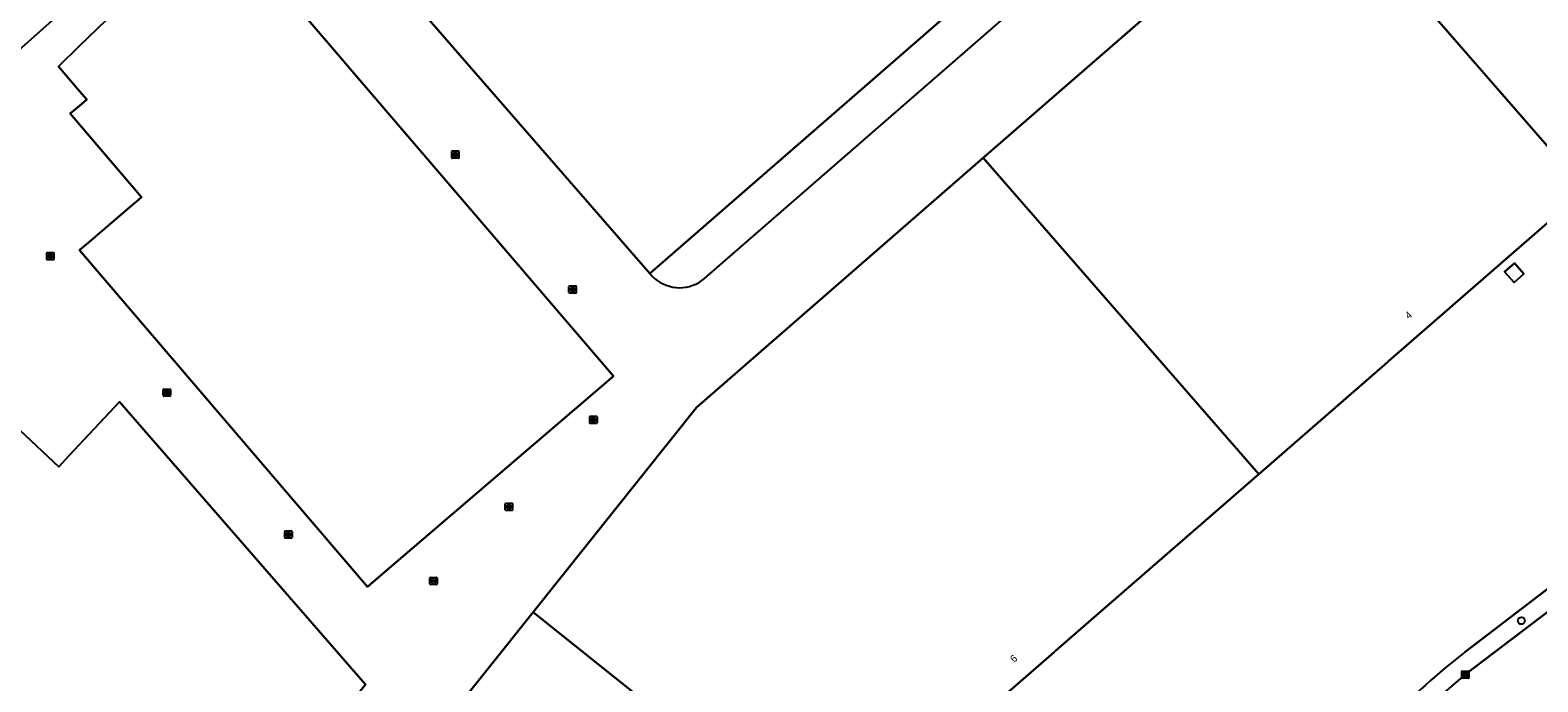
# Model space of a CAD drawing. Extents: x 156141 to 158132, y 385651 to 388333.
# Drawn here: x 156493.2 to 156702, y 386736.2 to 386826.5 of the extents above; entities that cross this region are included whole.
import ezdxf

# ---------------------------------------------------------------- set-up
doc = ezdxf.new("R2010")
doc.units = 0
for name, color, linetype in [('IMGEO_Berm_groen', 7, 'Continuous'), ('IMGEO_Boom', 7, 'Continuous'), ('IMGEO_Erf', 7, 'Continuous'), ('IMGEO_Groenvoorziening', 7, 'Continuous'), ('IMGEO_Hek', 7, 'Continuous'), ('IMGEO_Kolk', 7, 'Continuous'), ('IMGEO_Pand', 7, 'Continuous'), ('IMGEO_Pand_nummerreeks', 7, 'Continuous'), ('IMGEO_Pand_overbouw', 7, 'Continuous'), ('IMGEO_Rijbaan_lokaal_gesloten', 7, 'Continuous')]:
    doc.layers.add(name, color=color, linetype=linetype)

msp = doc.modelspace()

# ---------------------------------------------------------------- linework, layer by layer
at = {"layer": 'IMGEO_Berm_groen'}
for points in [[(156722.66, 386763.82), (156691.88, 386740.27)], [(156691.95, 386737.17), (156708.78, 386750), (156709.03, 386750.19), (156722.91, 386760.79)]]:
    msp.add_lwpolyline(points, dxfattribs=at)
for centre, radius, start, end in [((156758.44, 386655), 108.18, 127.9738, 143.0297), ((156759.5, 386654.29), 106.93, 129.1834, 140.1505)]:
    msp.add_arc(centre, radius, start, end, dxfattribs=at)
at = {"layer": 'IMGEO_Boom'}
msp.add_circle((156699.72, 386744.63), 0.489, dxfattribs=at)
at = {"layer": 'IMGEO_Erf'}
for points in [[(156579, 386792.74), (156536.65, 386841.45), (156528.4, 386850.93), (156539.01, 386860.16), (156540.51, 386861.46), (156539.64, 386862.47), (156541.88, 386864.4), (156542.76, 386863.4), (156544.26, 386864.71), (156553.86, 386857.56), (156554.4, 386856.9), (156564.64, 386845.13), (156582.75, 386860.85), (156583.79, 386861.76), (156573.53, 386873.55), (156565.27, 386883.02), (156568.32, 386885.63), (156567.99, 386886), (156571.25, 386888.77), (156592.61, 386907.35), (156643.5, 386848.89)], [(156562.82, 386745.82), (156585.47, 386774.18), (156625.19, 386808.77), (156670.44, 386848.17), (156724.8, 386895.5), (156762.97, 386851.71), (156754.18, 386844.05), (156753.97, 386843.86), (156725.69, 386819.23), (156725.5, 386819.06), (156708.6, 386804.34), (156681.33, 386780.59), (156681.14, 386780.43), (156663.35, 386764.94), (156635.2, 386740.45), (156635.02, 386740.29), (156627.59, 386733.83), (156608.17, 386709.52), (156594.29, 386692.16), (156594.13, 386691.97), (156570.73, 386662.69), (156570.57, 386662.48), (156563.29, 386653.38), (156517.91, 386689.59)], [(156573.96, 386778.5), (156540.63, 386750), (156539.88, 386749.35), (156539.32, 386750), (156500.02, 386795.98), (156500.69, 386796.56), (156500.87, 386796.72), (156507.65, 386802.53), (156507.84, 386802.69), (156508.6, 386803.34), (156500, 386813.38), (156498.7, 386814.9), (156500, 386815.99), (156501.01, 386816.84), (156500, 386818.01), (156497.07, 386821.42), (156500, 386824.27), (156502.48, 386826.69), (156506.95, 386831.05), (156513.62, 386837.54), (156518.51, 386831.86), (156524.17, 386836.69)], [(156698.75, 386794.18), (156700.06, 386792.68), (156698.71, 386791.5), (156697.4, 386793)]]:
    msp.add_lwpolyline(points, close=True, dxfattribs=at)
for points in [[(156500, 386831.2), (156491.57, 386823.65), (156483.14, 386815.4), (156480.48, 386812.82), (156481.2, 386811.98), (156475.71, 386805.5), (156458.53, 386785.23), (156416.67, 386732.53), (156478.51, 386695.24), (156485.28, 386691.16), (156502.21, 386680.95), (156502.3, 386681.12), (156504.13, 386680.02), (156508.42, 386677.43), (156596.8, 386624.11)], [(156440.94, 386745.41), (156441.14, 386745.62), (156436.99, 386749.49), (156473.36, 386788.27), (156497.13, 386765.98)], [(156497.13, 386765.98), (156498.54, 386767.48), (156505.52, 386774.95), (156539.63, 386735.79), (156502.86, 386689.7), (156473.05, 386707.68), (156477.03, 386711.95), (156467.31, 386721.05), (156467.13, 386720.89), (156467.24, 386720.39)], [(156691.88, 386740.27), (156722.66, 386763.82)]]:
    msp.add_lwpolyline(points, dxfattribs=at)
msp.add_arc((156758.44, 386655), 108.18, 127.9738, 143.0297, dxfattribs=at)
at = {"layer": 'IMGEO_Groenvoorziening'}
msp.add_lwpolyline([(156484.3, 386831.99), (156487.09, 386828.79), (156488.42, 386827.26), (156491.57, 386823.65), (156500, 386831.2), (156500.6, 386831.73), (156507.07, 386837.56), (156510.79, 386840.87), (156506.2, 386846.18)], dxfattribs=at)
at = {"layer": 'IMGEO_Hek'}
msp.add_lwpolyline([(156722.66, 386763.82), (156691.88, 386740.27)], dxfattribs=at)
msp.add_arc((156758.44, 386655), 108.18, 127.9738, 143.0297, dxfattribs=at)
at = {"layer": 'IMGEO_Kolk'}
for p, q in [((156551.56, 386808.8), (156551.56, 386809.65)), ((156551.64, 386809.72), (156552.49, 386809.72)), ((156552.49, 386808.72), (156551.64, 386808.72)), ((156551.82, 386809.22), (156551.82, 386809.23)), ((156551.86, 386809.27), (156552.26, 386809.27)), ((156552.26, 386809.18), (156551.86, 386809.18)), ((156552.05, 386809.5), (156552.08, 386809.5)), ((156552.07, 386808.94), (156552.05, 386808.94)), ((156552.31, 386809.23), (156552.31, 386809.22)), ((156552.56, 386809.65), (156552.56, 386808.8)), ((156495.46, 386794.72), (156495.46, 386795.57)), ((156495.53, 386795.64), (156496.38, 386795.64)), ((156496.38, 386794.64), (156495.53, 386794.64)), ((156495.71, 386795.14), (156495.71, 386795.15)), ((156496.15, 386795.1), (156495.75, 386795.1)), ((156495.76, 386795.19), (156496.16, 386795.19)), ((156495.94, 386795.42), (156495.97, 386795.42)), ((156495.97, 386794.86), (156495.94, 386794.86)), ((156496.2, 386795.15), (156496.2, 386795.14)), ((156496.46, 386795.57), (156496.46, 386794.72)), ((156567.8, 386790.11), (156567.8, 386790.96)), ((156567.87, 386791.04), (156568.72, 386791.04)), ((156568.72, 386790.04), (156567.87, 386790.04)), ((156568.05, 386790.53), (156568.05, 386790.54)), ((156568.49, 386790.49), (156568.09, 386790.49)), ((156568.1, 386790.58), (156568.5, 386790.58)), ((156568.28, 386790.82), (156568.31, 386790.82)), ((156568.31, 386790.26), (156568.28, 386790.26)), ((156568.54, 386790.54), (156568.54, 386790.53)), ((156568.8, 386790.96), (156568.8, 386790.11)), ((156511.6, 386775.82), (156511.6, 386776.67)), ((156511.67, 386776.74), (156512.52, 386776.74)), ((156512.52, 386775.74), (156511.67, 386775.74)), ((156511.86, 386776.24), (156511.86, 386776.25)), ((156511.9, 386776.29), (156512.3, 386776.29)), ((156512.29, 386776.2), (156511.9, 386776.2)), ((156512.11, 386775.96), (156512.08, 386775.96)), ((156512.09, 386776.52), (156512.11, 386776.52)), ((156512.34, 386776.25), (156512.34, 386776.24)), ((156512.6, 386776.67), (156512.6, 386775.82)), ((156570.68, 386772.05), (156570.68, 386772.9)), ((156570.75, 386772.98), (156571.6, 386772.98)), ((156571.6, 386771.98), (156570.75, 386771.98)), ((156570.93, 386772.47), (156570.93, 386772.48)), ((156571.37, 386772.43), (156570.97, 386772.43)), ((156570.98, 386772.52), (156571.37, 386772.52)), ((156571.16, 386772.76), (156571.19, 386772.76)), ((156571.19, 386772.2), (156571.16, 386772.2)), ((156571.42, 386772.48), (156571.42, 386772.47)), ((156571.68, 386772.9), (156571.68, 386772.05)), ((156558.98, 386759.99), (156558.98, 386760.84)), ((156559.06, 386760.92), (156559.91, 386760.92)), ((156559.47, 386760.7), (156559.5, 386760.7)), ((156559.98, 386760.84), (156559.98, 386759.99)), ((156559.91, 386759.92), (156559.06, 386759.92)), ((156559.24, 386760.41), (156559.24, 386760.42)), ((156559.28, 386760.46), (156559.68, 386760.46)), ((156559.68, 386760.37), (156559.28, 386760.37)), ((156559.49, 386760.14), (156559.47, 386760.14)), ((156559.73, 386760.42), (156559.73, 386760.41)), ((156528.44, 386756.16), (156528.44, 386757.01)), ((156528.51, 386757.08), (156529.36, 386757.08)), ((156528.69, 386756.58), (156528.69, 386756.59)), ((156529.13, 386756.54), (156528.73, 386756.54)), ((156528.74, 386756.63), (156529.13, 386756.63)), ((156528.92, 386756.86), (156528.95, 386756.86)), ((156528.95, 386756.3), (156528.92, 386756.3)), ((156529.18, 386756.59), (156529.18, 386756.58)), ((156529.44, 386757.01), (156529.44, 386756.16)), ((156529.36, 386756.08), (156528.51, 386756.08)), ((156548.54, 386749.71), (156548.54, 386750.57)), ((156548.61, 386750.64), (156549.47, 386750.64)), ((156548.8, 386750.13), (156548.8, 386750.15)), ((156548.84, 386750.18), (156549.24, 386750.18)), ((156549.23, 386750.1), (156548.84, 386750.1)), ((156549.03, 386750.42), (156549.05, 386750.42)), ((156549.28, 386750.15), (156549.28, 386750.13)), ((156549.54, 386750.57), (156549.54, 386749.71)), ((156549.47, 386749.64), (156548.61, 386749.64)), ((156549.05, 386749.86), (156549.02, 386749.86)), ((156691.46, 386736.75), (156691.46, 386737.6)), ((156691.53, 386737.67), (156692.38, 386737.67)), ((156692.46, 386737.6), (156692.46, 386736.75)), ((156692.38, 386736.67), (156691.53, 386736.67)), ((156691.71, 386737.17), (156691.71, 386737.18)), ((156692.15, 386737.13), (156691.75, 386737.13)), ((156691.76, 386737.22), (156692.15, 386737.22)), ((156691.94, 386737.45), (156691.97, 386737.45)), ((156691.97, 386736.89), (156691.94, 386736.89)), ((156692.2, 386737.18), (156692.2, 386737.17))]:
    msp.add_line(p, q, dxfattribs=at)
for points in [[(156551.56, 386808.8), (156551.56, 386809.65)], [(156551.64, 386809.72), (156552.49, 386809.72)], [(156552.49, 386808.72), (156551.64, 386808.72)], [(156552.56, 386809.65), (156552.56, 386808.8)], [(156495.46, 386794.72), (156495.46, 386795.57)], [(156495.53, 386795.64), (156496.38, 386795.64)], [(156496.38, 386794.64), (156495.53, 386794.64)], [(156496.46, 386795.57), (156496.46, 386794.72)], [(156567.8, 386790.11), (156567.8, 386790.96)], [(156567.87, 386791.04), (156568.72, 386791.04)], [(156568.72, 386790.04), (156567.87, 386790.04)], [(156568.8, 386790.96), (156568.8, 386790.11)], [(156511.6, 386775.82), (156511.6, 386776.67)], [(156511.67, 386776.74), (156512.52, 386776.74)], [(156512.52, 386775.74), (156511.67, 386775.74)], [(156512.6, 386776.67), (156512.6, 386775.82)], [(156570.68, 386772.05), (156570.68, 386772.9)], [(156570.75, 386772.98), (156571.6, 386772.98)], [(156571.6, 386771.98), (156570.75, 386771.98)], [(156571.68, 386772.9), (156571.68, 386772.05)], [(156558.98, 386759.99), (156558.98, 386760.84)], [(156559.06, 386760.92), (156559.91, 386760.92)], [(156559.98, 386760.84), (156559.98, 386759.99)], [(156559.91, 386759.92), (156559.06, 386759.92)], [(156528.44, 386756.16), (156528.44, 386757.01)], [(156528.51, 386757.08), (156529.36, 386757.08)], [(156529.44, 386757.01), (156529.44, 386756.16)], [(156529.36, 386756.08), (156528.51, 386756.08)], [(156548.54, 386749.71), (156548.54, 386750.57)], [(156548.61, 386750.64), (156549.47, 386750.64)], [(156549.54, 386750.57), (156549.54, 386749.71)], [(156549.47, 386749.64), (156548.61, 386749.64)], [(156691.46, 386736.75), (156691.46, 386737.6)], [(156691.53, 386737.67), (156692.38, 386737.67)], [(156692.46, 386737.6), (156692.46, 386736.75)], [(156692.38, 386736.67), (156691.53, 386736.67)]]:
    msp.add_lwpolyline(points, dxfattribs=at)
for centre, radius, start, end in [((156551.64, 386809.65), 0.0765, 91.552, 178.448), ((156551.64, 386809.65), 0.0765, 91.552, 178.448), ((156551.64, 386808.8), 0.0765, 181.552, 268.448), ((156551.64, 386808.8), 0.0765, 181.552, 268.448), ((156551.86, 386809.23), 0.0403, 85.8775, 175.7526), ((156551.86, 386809.22), 0.0366, 178.938, 274.7102), ((156552.27, 386809.23), 0.0386, 1.7309, 96.639), ((156552.26, 386809.22), 0.043, 264.8664, 352.4533), ((156552.49, 386809.65), 0.0765, 1.552, 88.448), ((156552.49, 386809.65), 0.0765, 1.552, 88.448), ((156552.49, 386808.8), 0.0765, 271.552, 358.448), ((156552.49, 386808.8), 0.0765, 271.552, 358.448), ((156495.53, 386795.57), 0.0765, 91.552, 178.448), ((156495.53, 386795.57), 0.0765, 91.552, 178.448), ((156495.53, 386794.72), 0.0765, 181.552, 268.448), ((156495.53, 386794.72), 0.0765, 181.552, 268.448), ((156495.76, 386795.15), 0.0403, 85.8775, 175.7526), ((156495.75, 386795.14), 0.0366, 178.938, 274.7102), ((156496.16, 386795.14), 0.043, 264.8664, 352.4533), ((156496.16, 386795.15), 0.0386, 1.7309, 96.639), ((156496.38, 386795.57), 0.0765, 1.552, 88.448), ((156496.38, 386795.57), 0.0765, 1.552, 88.448), ((156496.38, 386794.72), 0.0765, 271.552, 358.448), ((156496.38, 386794.72), 0.0765, 271.552, 358.448), ((156567.87, 386790.96), 0.0765, 91.552, 178.448), ((156567.87, 386790.96), 0.0765, 91.552, 178.448), ((156567.87, 386790.11), 0.0765, 181.552, 268.448), ((156567.87, 386790.11), 0.0765, 181.552, 268.448), ((156568.1, 386790.54), 0.0403, 85.8775, 175.7526), ((156568.09, 386790.53), 0.0366, 178.938, 274.7102), ((156568.5, 386790.54), 0.043, 264.8664, 352.4533), ((156568.5, 386790.54), 0.0386, 1.7309, 96.639), ((156568.72, 386790.96), 0.0765, 1.552, 88.448), ((156568.72, 386790.96), 0.0765, 1.552, 88.448), ((156568.72, 386790.11), 0.0765, 271.552, 358.448), ((156568.72, 386790.11), 0.0765, 271.552, 358.448), ((156511.67, 386776.67), 0.0765, 91.552, 178.448), ((156511.67, 386776.67), 0.0765, 91.552, 178.448), ((156511.67, 386775.82), 0.0765, 181.552, 268.448), ((156511.67, 386775.82), 0.0765, 181.552, 268.448), ((156511.9, 386776.25), 0.0403, 85.8775, 175.7526), ((156511.89, 386776.24), 0.0366, 178.938, 274.7102), ((156512.3, 386776.24), 0.043, 264.8664, 352.4533), ((156512.3, 386776.25), 0.0386, 1.7309, 96.639), ((156512.52, 386776.67), 0.0765, 1.552, 88.448), ((156512.52, 386776.67), 0.0765, 1.552, 88.448), ((156512.52, 386775.82), 0.0765, 271.552, 358.448), ((156512.52, 386775.82), 0.0765, 271.552, 358.448), ((156570.75, 386772.9), 0.0765, 91.552, 178.448), ((156570.75, 386772.9), 0.0765, 91.552, 178.448), ((156570.75, 386772.05), 0.0765, 181.552, 268.448), ((156570.75, 386772.05), 0.0765, 181.552, 268.448), ((156570.97, 386772.48), 0.0403, 85.8775, 175.7526), ((156570.97, 386772.47), 0.0366, 178.938, 274.7102), ((156571.38, 386772.48), 0.0386, 1.7309, 96.639), ((156571.38, 386772.48), 0.043, 264.8664, 352.4533), ((156571.6, 386772.9), 0.0765, 1.552, 88.448), ((156571.6, 386772.9), 0.0765, 1.552, 88.448), ((156571.6, 386772.05), 0.0765, 271.552, 358.448), ((156571.6, 386772.05), 0.0765, 271.552, 358.448), ((156559.06, 386760.84), 0.0765, 91.552, 178.448), ((156559.06, 386760.84), 0.0765, 91.552, 178.448), ((156559.91, 386760.84), 0.0765, 1.552, 88.448), ((156559.91, 386760.84), 0.0765, 1.552, 88.448), ((156559.06, 386759.99), 0.0765, 181.552, 268.448), ((156559.06, 386759.99), 0.0765, 181.552, 268.448), ((156559.28, 386760.42), 0.0403, 85.8775, 175.7526), ((156559.28, 386760.41), 0.0366, 178.938, 274.7102), ((156559.69, 386760.42), 0.0386, 1.7309, 96.639), ((156559.68, 386760.42), 0.043, 264.8664, 352.4533), ((156559.91, 386759.99), 0.0765, 271.552, 358.448), ((156559.91, 386759.99), 0.0765, 271.552, 358.448), ((156528.51, 386757.01), 0.0765, 91.552, 178.448), ((156528.51, 386757.01), 0.0765, 91.552, 178.448), ((156528.73, 386756.59), 0.0403, 85.8775, 175.7526), ((156528.73, 386756.58), 0.0366, 178.938, 274.7102), ((156529.14, 386756.59), 0.0386, 1.7309, 96.639), ((156529.14, 386756.58), 0.043, 264.8664, 352.4533), ((156529.36, 386757.01), 0.0765, 1.552, 88.448), ((156529.36, 386757.01), 0.0765, 1.552, 88.448), ((156528.51, 386756.16), 0.0765, 181.552, 268.448), ((156528.51, 386756.16), 0.0765, 181.552, 268.448), ((156529.36, 386756.16), 0.0765, 271.552, 358.448), ((156529.36, 386756.16), 0.0765, 271.552, 358.448), ((156548.61, 386750.56), 0.0765, 91.552, 178.448), ((156548.61, 386750.56), 0.0765, 91.552, 178.448), ((156548.84, 386750.14), 0.0403, 85.8775, 175.7526), ((156548.83, 386750.13), 0.0366, 178.938, 274.7102), ((156549.24, 386750.14), 0.043, 264.8664, 352.4533), ((156549.24, 386750.14), 0.0386, 1.7309, 96.639), ((156549.46, 386750.56), 0.0765, 1.552, 88.448), ((156549.46, 386750.56), 0.0765, 1.552, 88.448), ((156548.61, 386749.71), 0.0765, 181.552, 268.448), ((156548.61, 386749.71), 0.0765, 181.552, 268.448), ((156549.46, 386749.71), 0.0765, 271.552, 358.448), ((156549.46, 386749.71), 0.0765, 271.552, 358.448), ((156691.53, 386737.6), 0.0765, 91.552, 178.448), ((156691.53, 386737.6), 0.0765, 91.552, 178.448), ((156692.38, 386737.6), 0.0765, 1.552, 88.448), ((156692.38, 386737.6), 0.0765, 1.552, 88.448), ((156691.53, 386736.75), 0.0765, 181.552, 268.448), ((156691.53, 386736.75), 0.0765, 181.552, 268.448), ((156691.75, 386737.18), 0.0403, 85.8775, 175.7526), ((156691.75, 386737.17), 0.0366, 178.938, 274.7102), ((156692.16, 386737.18), 0.0386, 1.7309, 96.639), ((156692.16, 386737.17), 0.043, 264.8664, 352.4533), ((156692.38, 386736.75), 0.0765, 271.552, 358.448), ((156692.38, 386736.75), 0.0765, 271.552, 358.448)]:
    msp.add_arc(centre, radius, start, end, dxfattribs=at)
for centre, major_axis, ratio, start_param, end_param in [((156552.05, 386809.22), (-0.387, 0.002), 0.722429, 4.712389, 7.853982), ((156552.07, 386809.22), (-0.39, 0.002), 0.717154, 1.570796, 4.712389), ((156495.94, 386795.14), (-0.387, 0.002), 0.722429, 4.712389, 7.853982), ((156495.97, 386795.14), (-0.39, 0.002), 0.717154, 1.570796, 4.712389), ((156568.28, 386790.54), (-0.387, 0.002), 0.722429, 4.712389, 7.853982), ((156568.31, 386790.54), (-0.39, 0.002), 0.717154, 1.570796, 4.712389), ((156512.08, 386776.24), (-0.387, 0.002), 0.722429, 4.712389, 7.853982), ((156512.11, 386776.24), (-0.39, 0.002), 0.717154, 1.570796, 4.712389), ((156571.16, 386772.48), (-0.387, 0.002), 0.722429, 4.712389, 7.853982), ((156571.19, 386772.48), (-0.39, 0.002), 0.717154, 1.570796, 4.712389), ((156559.47, 386760.42), (-0.387, 0.002), 0.722429, 4.712389, 7.853982), ((156559.49, 386760.42), (-0.39, 0.002), 0.717154, 1.570796, 4.712389), ((156528.92, 386756.58), (-0.387, 0.002), 0.722429, 4.712389, 7.853982), ((156528.95, 386756.58), (-0.39, 0.002), 0.717154, 1.570796, 4.712389), ((156549.03, 386750.14), (-0.387, 0.002), 0.722429, 4.712389, 7.853982), ((156549.05, 386750.14), (-0.39, 0.002), 0.717154, 1.570796, 4.712389), ((156691.94, 386737.17), (-0.387, 0.002), 0.722429, 4.712389, 7.853982), ((156691.97, 386737.17), (-0.39, 0.002), 0.717154, 1.570796, 4.712389)]:
    msp.add_ellipse(centre, major_axis=major_axis, ratio=ratio, start_param=start_param, end_param=end_param, dxfattribs=at)
at = {"layer": 'IMGEO_Pand'}
for points in [[(156579, 386792.74), (156643.5, 386848.89), (156592.61, 386907.35), (156571.25, 386888.77), (156567.99, 386886), (156568.32, 386885.63), (156565.27, 386883.02), (156573.53, 386873.55), (156583.79, 386861.76), (156582.75, 386860.85), (156564.64, 386845.13), (156554.4, 386856.9), (156553.86, 386857.56), (156544.26, 386864.71), (156542.76, 386863.4), (156541.88, 386864.4), (156539.64, 386862.47), (156540.51, 386861.46), (156539.01, 386860.16), (156528.4, 386850.93), (156536.65, 386841.45)], [(156670.44, 386848.17), (156708.6, 386804.34), (156725.5, 386819.06), (156725.69, 386819.23), (156753.97, 386843.86), (156754.18, 386844.05), (156762.97, 386851.71), (156724.8, 386895.5)], [(156663.35, 386764.94), (156681.14, 386780.43), (156681.33, 386780.59), (156708.6, 386804.34), (156670.44, 386848.17), (156625.19, 386808.77)], [(156573.96, 386778.5), (156524.17, 386836.69), (156518.51, 386831.86), (156513.62, 386837.54), (156506.95, 386831.05), (156502.48, 386826.69), (156500, 386824.27), (156497.07, 386821.42), (156500, 386818.01), (156501.01, 386816.84), (156500, 386815.99), (156498.7, 386814.9), (156500, 386813.38), (156508.6, 386803.34), (156507.84, 386802.69), (156507.65, 386802.53), (156500.87, 386796.72), (156500.69, 386796.56), (156500.02, 386795.98), (156539.32, 386750), (156539.88, 386749.35), (156540.63, 386750)], [(156562.82, 386745.82), (156608.17, 386709.52), (156627.59, 386733.83), (156635.02, 386740.29), (156635.2, 386740.45), (156663.35, 386764.94), (156625.19, 386808.77), (156585.47, 386774.18)], [(156698.71, 386791.5), (156700.06, 386792.68), (156698.75, 386794.18), (156697.4, 386793)], [(156562.82, 386745.82), (156517.91, 386689.59), (156563.29, 386653.38), (156570.57, 386662.48), (156570.73, 386662.69), (156594.13, 386691.97), (156594.29, 386692.16), (156608.17, 386709.52)]]:
    msp.add_lwpolyline(points, close=True, dxfattribs=at)
msp.add_lwpolyline([(156467.24, 386720.39), (156467.13, 386720.89), (156467.31, 386721.05), (156477.03, 386711.95), (156473.05, 386707.68), (156502.86, 386689.7), (156539.63, 386735.79), (156505.52, 386774.95), (156498.54, 386767.48), (156497.13, 386765.98), (156473.36, 386788.27), (156436.99, 386749.49), (156441.14, 386745.62), (156440.94, 386745.41)], dxfattribs=at)
at = {"layer": 'IMGEO_Pand_overbouw'}
msp.add_lwpolyline([(156643.5, 386848.89), (156579, 386792.74), (156579.31, 386792.39), (156579.65, 386792.07), (156580.02, 386791.78), (156580.42, 386791.52), (156580.83, 386791.3), (156581.27, 386791.11), (156581.71, 386790.97), (156582.17, 386790.86), (156582.64, 386790.8), (156583.11, 386790.78), (156583.58, 386790.8), (156584.05, 386790.86), (156584.51, 386790.96), (156584.96, 386791.11), (156585.39, 386791.29), (156585.81, 386791.51), (156586.2, 386791.77), (156586.57, 386792.06), (156643.21, 386841.38)], dxfattribs=at)
at = {"layer": 'IMGEO_Rijbaan_lokaal_gesloten'}
msp.add_lwpolyline([(156722.91, 386760.79), (156709.03, 386750.19), (156708.78, 386750), (156691.95, 386737.17)], dxfattribs=at)
msp.add_arc((156759.5, 386654.29), 106.93, 129.1834, 140.1505, dxfattribs=at)

# ---------------------------------------------------------------- texts
at = {"layer": 'IMGEO_Pand_nummerreeks'}
for s, rotation, p in [('4', 41.0387, (156684.12, 386786.36)), ('6', 41.0321, (156629.44, 386738.78))]:
    msp.add_text(s, height=1, rotation=rotation, dxfattribs=at).set_placement(p)

doc.saveas('drawing.dxf')
